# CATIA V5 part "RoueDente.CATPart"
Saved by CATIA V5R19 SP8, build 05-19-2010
Part number: pignon1
Source: Unknown
Publications: "Esquisse.8", "Plan.3"
Material "Rouge DS": density 7860 kg/m3, Young's modulus 2e+11 Pa, Poisson ratio 0.266
Bounding box of the stored display mesh (mm): x 0 to 5, y -20.499 to 20.499, z -20.499 to 20.499
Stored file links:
  E:\EDELI\gcausse\Edeli_2012_190_gcausse\RoueDente.CATPart
  C:\usr\gt1\projet\site_web\doc\catia\gears\spur_gear_files\parts\gear_n.CATPart
  C:\Users\thinkmotion1\Desktop\Nouveau dossier\Cremai_Automobile\Cremaillere_automobile.CATProduct
  C:\Program Files\Dassault Systemes\B20\win_b64\startup\materials\French\Catalog.CATMaterial
  C:\Program Files\Dassault Systemes\B20\win_b64\startup\materials\red_env_512x512.jpg
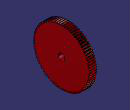
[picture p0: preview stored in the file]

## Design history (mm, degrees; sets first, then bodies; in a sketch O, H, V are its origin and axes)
Parameters
  a = 20 deg
  m = 0.5 mm
  Z = 80
  rp = 20 mm {= m * Z / 2}
  ra = 20.5 mm {= rp + m}
  rb = 18.7939 mm {= rp * cos( a )}
  rf = 19.375 mm {= rp - 1.25 * m}
  rc = 0.19 mm {= m * 0.38}
  c = 0.115855 {= sqrt( 1 / ( cos( a ) * cos( a ) ) - 1 ) / PI}
  phi = 1.979 deg
  `diametre perçages extérieurs` = 35 mm
Set1
  DatumCurve1: linked copy from another document
Set2
  Line1 "Axe X": stored without definition
  Plane1: type Angle, RefPlane zx-plane, Direction Line1, Angle 2.25 {= 180deg / Z}
  Point1 "origine": (0, 0, 0)
  Point2: (0, 0, 18.7939)
  Point3: (0, 0.1923, 19.6985)
  Point4: (0, 1.4935, 22.1454)
  Point5: (0, 4.7932, 25.3767)
  Point6: (0, 10.5759, 28.2688)
  Curve1: Elements (Point2; Point3; Point4; Point5; Point6)
  Extrapol1: ToExtrapol Point2, Support Curve1, Length 1 {= m * 2}
  Rotate1: ToTransfor Extrapol1, Axis Line1, Angle 1.979 {= phi}
  Circle1: type CtrRad, Start 0, End 180, Center Point1, Support yz-plane, Radius 19.375 {= rf}, FirstDirection (0, 1, 0)
  Circle2: type CtrRad, Start 0, End 180, Center Point1, Support yz-plane, Radius 20.5 {= ra}, FirstDirection (0, 1, 0)
  Corner1: Element1 Rotate1, Element2 Circle1, Radius 0.19 {= rc}
  Symmetry1: ToTransfor Corner1, Reference Plane1
  Split1: ToCut Rotate1, Cutting (Corner1; Circle2)
  Symmetry2: ToTransfor Split1, Reference zx-plane
  Circle3: type 2PointsRad, Start 0, End 180, FirstPoint vertex of Symmetry1, SecondPoint vertex of Corner1, Support yz-plane, Radius 19.375 {= rf}
  Circle4: type 2PointsRad, Start 0, End 180, FirstPoint vertex of Split1, SecondPoint vertex of Symmetry2, Support yz-plane, Radius 20.5 {= ra}
  Join1: Elements (Symmetry1; Circle3; Corner1; Split1; Circle4; Symmetry2)
  CircPattern1: of Join1, instances 80 {= Z}, angular step 4.5 {= 360.0*1 deg/CircPattern1.AngularNumber}, axis from Line1
  Join2: Elements (Join1; CircPattern1)
  Plane2: type Offset, RefPlane yz-plane, Offset 33
  Sketch1 on start face of Pad1, origin (0, 0, 0), H (0, -1, 0), V (0, 0, 1)
    circle A1 centre (0, 0) radius 2.5
    radius A1 = 2.5
Body1 (main body)
  Pad1: profile Join2, length 5
  Sketch2 on Plane2, origin (33, 0, 0), H (0, 1, 0), V (0, 0, 1)
    circle A1 centre (0, 0) radius 31.6677
    radius A1 = 31.6677
  Sketch3 on start face of Pad1, origin (0, 0, 0), H (0, -1, 0), V (0, 0, 1)
    circle A1 centre (0, 0) radius 10
    radius A1 = 10
  Sketch4 on end face of Pad1, origin (5, 0, 0), H (0, 1, 0), V (0, 0, 1)
    circle A1 centre (0, 0) radius 10
    radius A1 = 10
  Pocket1: profile Sketch1, direction (1, 0, 0), length 5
